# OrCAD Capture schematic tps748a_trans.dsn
size A
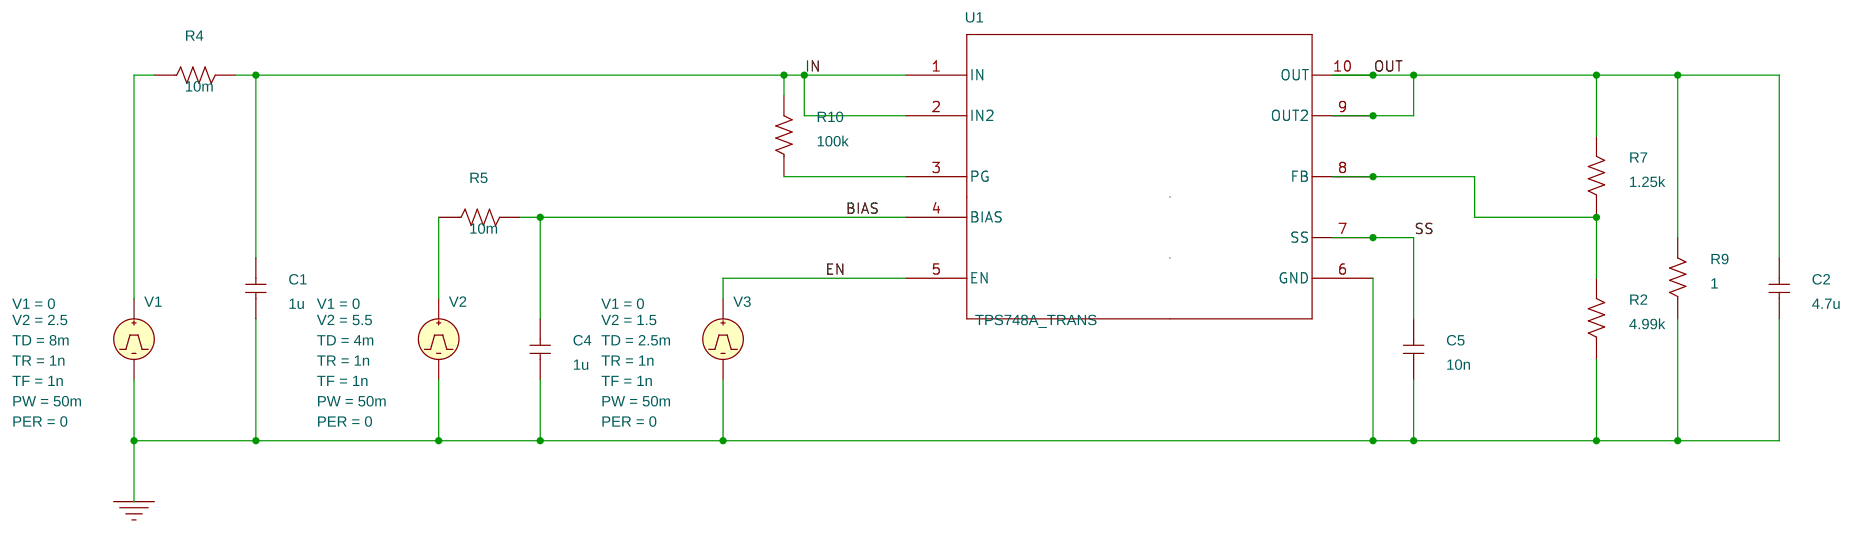
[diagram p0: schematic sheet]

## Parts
C1  1u  [RAD/CK05]
C2  4.7u  [RAD/CK05]
C4  1u  [RAD/CK05]
C5  10n  [RAD/CK05]
R2  4.99k  [AX/RC05]
R4  10m  [AX/RC05]
R5  10m  [AX/RC05]
R7  1.25k  [AX/RC05]
R9  1  [AX/RC05]
R10  100k  [AX/RC05]
U1  TPS748A_TRANS
V1  VPULSE
V2  VPULSE
V3  VPULSE

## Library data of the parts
C1 C2 C4 C5 = C
R2 R4 R5 R7 R9 R10 = R
U1 = TPS748A_TRANS
V1 = VPULSE: PER: 0; PW: 50m; TD: 8m; TF: 1n; TR: 1n; V1: 0; V2: 2.5
V2 = VPULSE: PER: 0; PW: 50m; TD: 4m; TF: 1n; TR: 1n; V1: 0; V2: 5.5
V3 = VPULSE: PER: 0; PW: 50m; TD: 2.5m; TF: 1n; TR: 1n; V1: 0; V2: 1.5

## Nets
0: C1.1 C2.1 C4.1 C5.1 R2.1 R9.1 U1.6(GND) V1.2(-) V2.2(-) V3.2(-)
BIAS: C4.2 R5.2 U1.4(BIAS)
EN: U1.5(EN) V3.1(+)
IN: C1.2 R4.2 R10.2 U1.1(IN) U1.2(IN2)
OUT: C2.2 R7.2 R9.2 U1.9(OUT2) U1.10(OUT)
SS: C5.2 U1.7(SS)
N286715: R4.1 V1.1(+)
N286773: R5.1 V2.1(+)
N287389: R2.2 R7.1 U1.8(FB)
N289180: R10.1 U1.3(PG)
